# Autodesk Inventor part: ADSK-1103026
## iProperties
Shininess: 41.0
Length Units: 11272
Angle Units: 11279
Time Units: 11290
Mass Units: 11286
Length Display Precision: 4
Angle Display Precision: 2
Compacted: True
Created: 2000-08
Part Number: ADSK-1103026
Document SubType Name: Modeling
Description: 24 TOOTH CLUTCH GEAR
Mass: 3.13134 g
Surface Area: 23.3651 cm^2
Volume: 1.15548 cm^3
Density: 2.71 g/cm^3
Material: Aluminum-6061
Density: 0.0
Volumn: 0.0
Area: 0.0
PropertySet Name: Model Information
Control State: 0
Master: False
Checked Out: False
Author: Autodesk, Inc.
